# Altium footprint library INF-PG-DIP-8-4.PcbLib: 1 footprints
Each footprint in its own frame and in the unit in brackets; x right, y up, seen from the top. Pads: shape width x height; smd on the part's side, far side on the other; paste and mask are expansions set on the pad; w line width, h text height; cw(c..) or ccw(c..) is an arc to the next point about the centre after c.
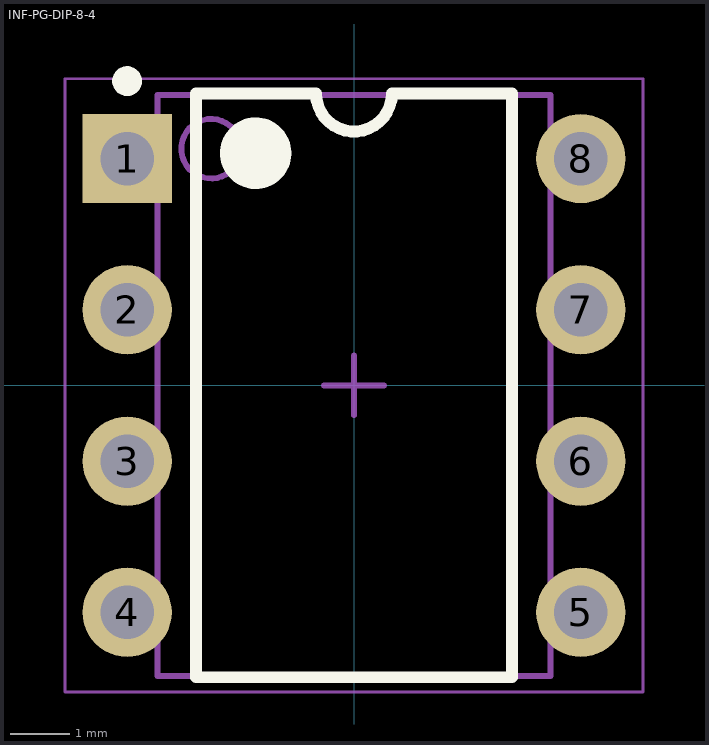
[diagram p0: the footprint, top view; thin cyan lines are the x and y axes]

## INF-PG-DIP-8-4 [mm] "DIP, 8-Leads, Body 9.52x6.35mm, Pitch 2.54mm"
height 4.37
pads (8):
  rect 1.5x1.5 hole 0.9: 1(-3.81,3.81)
  round 1.5 hole 0.9: 2(-3.81,1.27) 3(-3.81,-1.27) 4(-3.81,-3.81) 5(3.81,-3.81) 6(3.81,-1.27) 7(3.81,1.27) 8(3.81,3.81)
Top Overlay:
  circle w0.6: c-1.65,3.9 r0.3
  circle w0.25: c-3.81,5.11 r0.125
  lines w0.2: -2.65,-4.9 2.65,-4.9 2.65,4.9 0.635,4.9 cw(c0,4.9) -0.635,4.9 -2.65,4.9 -2.65,-4.9
Mechanical 13:
  circle w0.1: c-2.4,3.975 r0.5
  lines w0.1: -3.3,-4.875 3.3,-4.875 3.3,4.875 -3.3,4.875 -3.3,-4.875
Mechanical 15:
  lines w0.05: -4.85,-5.15 4.85,-5.15 4.85,5.15 -4.85,5.15 -4.85,-5.15
  lines w0.1: -0.5,0 0.5,0 ; 0,-0.5 0,0.5
3D body: height 4.37, standoff 0.38, extent -3.3,-4.875 3.3,4.875
3D body: height 0, standoff -1.6, extent 3.675,3.45 3.945,4.17
3D body: height 2.51, standoff 2.24, extent 3.3,3.31 3.945,4.31
3D body: height 2.24, standoff 0, extent 3.675,3.31 3.945,4.31
3D body: height 0, standoff -1.6, extent 3.675,0.91 3.945,1.63
3D body: height 2.51, standoff 2.24, extent 3.3,0.77 3.945,1.77
3D body: height 2.24, standoff 0, extent 3.675,0.77 3.945,1.77
3D body: height 0, standoff -1.6, extent 3.675,-1.63 3.945,-0.91
3D body: height 2.51, standoff 2.24, extent 3.3,-1.77 3.945,-0.77
3D body: height 2.24, standoff 0, extent 3.675,-1.77 3.945,-0.77
3D body: height 0, standoff -1.6, extent 3.675,-4.17 3.945,-3.45
3D body: height 2.51, standoff 2.24, extent 3.3,-4.31 3.945,-3.31
3D body: height 2.24, standoff 0, extent 3.675,-4.31 3.945,-3.31
3D body: height 0, standoff -1.6, extent -3.945,-4.17 -3.675,-3.45
3D body: height 2.51, standoff 2.24, extent -3.945,-4.31 -3.3,-3.31
3D body: height 2.24, standoff 0, extent -3.945,-4.31 -3.675,-3.31
3D body: height 0, standoff -1.6, extent -3.945,-1.63 -3.675,-0.91
3D body: height 2.51, standoff 2.24, extent -3.945,-1.77 -3.3,-0.77
3D body: height 2.24, standoff 0, extent -3.945,-1.77 -3.675,-0.77
3D body: height 0, standoff -1.6, extent -3.945,0.91 -3.675,1.63
3D body: height 2.51, standoff 2.24, extent -3.945,0.77 -3.3,1.77
3D body: height 2.24, standoff 0, extent -3.945,0.77 -3.675,1.77
3D body: height 0, standoff -1.6, extent -3.945,3.45 -3.675,4.17
3D body: height 2.51, standoff 2.24, extent -3.945,3.31 -3.3,4.31
3D body: height 2.24, standoff 0, extent -3.945,3.31 -3.675,4.31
